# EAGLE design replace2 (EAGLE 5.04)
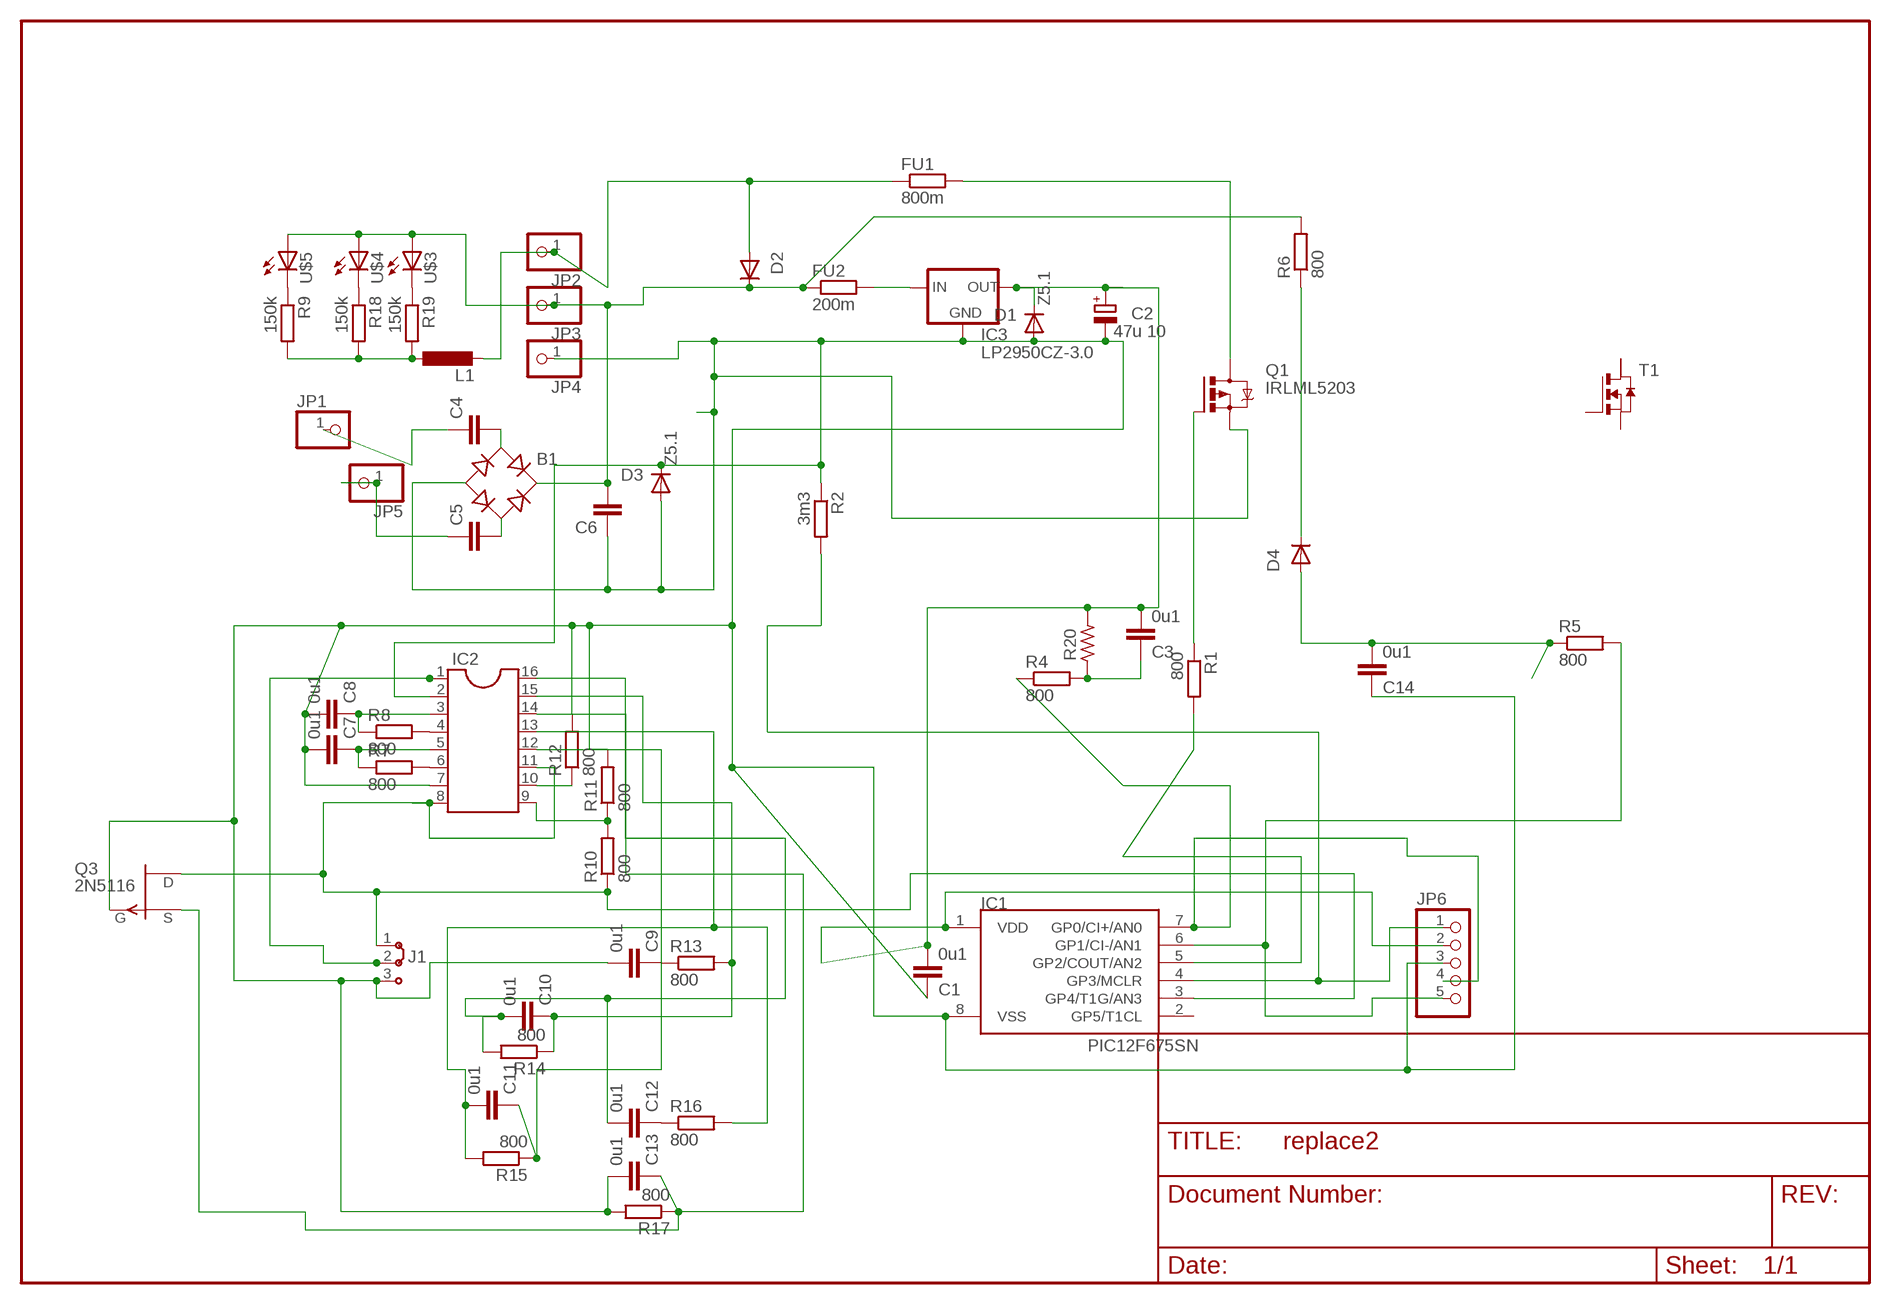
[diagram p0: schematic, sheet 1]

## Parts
B1  RB1A  [RB1A]
C1  0u1  C-EUC1206  [C1206]
C2  47u 10  CPOL-EUE2.5-5  [E2,5-5]
C3  0u1  C-EUC1206  [C1206]
C4  C-EU050-025X075  [C050-025X075]
C5  C-EU050-025X075  [C050-025X075]
C6  C-EU050-025X075  [C050-025X075]
C7  0u1  C-EUC1206  [C1206]
C8  0u1  C-EUC1206  [C1206]
C9  0u1  C-EUC1206  [C1206]
C10  0u1  C-EUC1206  [C1206]
C11  0u1  C-EUC1206  [C1206]
C12  0u1  C-EUC1206  [C1206]
C13  0u1  C-EUC1206  [C1206]
C14  0u1  C-EUC1206  [C1206]
D1  Z5.1  DIODE-MINIMELF  [MINIMELF]
D2  DIODE-MELF-MLL41  [MELF-MLL41]
D3  Z5.1  DIODE-MINIMELF  [MINIMELF]
D4  DIODE-MICROMELF-R  [MICROMELF-R]
FU1  800m  R-EU_0204/5  [0204/5]
FU2  200m  R-EU_0204/5  [0204/5]
IC1  PIC12F675SN  [SO-08]
IC2  DIL16  [DIL16]
IC3  LP2950CZ-3.0  [TO92]
J1  J2X2MM  [04C]
JP1  PINHD-1X1  [1X01]
JP2  PINHD-1X1  [1X01]
JP3  PINHD-1X1  [1X01]
JP4  PINHD-1X1  [1X01]
JP5  PINHD-1X1  [1X01]
JP6  PINHD-1X5  [1X05]
L1  L-EU0207/7  [0207/7]
Q1  IRLML5203  [MICRO3]
Q3  2N5116  [TO18]
R1  800  R-EU_R1206  [R1206]
R2  3m3  R-EU_R1206  [R1206]
R4  800  R-EU_R1206  [R1206]
R5  800  R-EU_R1206  [R1206]
R6  800  R-EU_R1206  [R1206]
R7  800  R-EU_R1206  [R1206]
R8  800  R-EU_R1206  [R1206]
R9  150k  R-EU_R1206  [R1206]
R10  800  R-EU_R1206  [R1206]
R11  800  R-EU_R1206  [R1206]
R12  800  R-EU_R1206  [R1206]
R13  800  R-EU_R1206  [R1206]
R14  800  R-EU_R1206  [R1206]
R15  800  R-EU_R1206  [R1206]
R16  800  R-EU_R1206  [R1206]
R17  800  R-EU_R1206  [R1206]
R18  150k  R-EU_R1206  [R1206]
R19  150k  R-EU_R1206  [R1206]
R20  R_X0207/5V  [0207/5V]
T1  NMOSSOT223  [SOT223]
U$3  LED5MM  [LED5MM]
U$4  LED5MM  [LED5MM]
U$5  LED5MM  [LED5MM]

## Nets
GND: B1.- C1.1 C2.- C6.1 C7.2 C8.2 C9.2 C13.2 C14.1 D1.A D3.A D3.C IC1.8(VSS) IC2.2 IC2.7 IC3.2(GND) J1.3 JP4.1 JP6.3 Q1.2(S) Q3.2(G) R2.1 R11.2 R12.2 R17.2
N$1: B1.+ C6.2 D2.C FU2.1 JP3.1 R6.2 U$3.A U$4.A U$5.A
N$4: D2.A FU1.1 JP2.1 L1.2
N$7: Q1.1(G) R1.1
N$8: FU2.2 IC3.3(IN)
N$9: FU1.2 Q1.3(D)
N$10: D4.C R6.1
N$12: IC1.4(GP3/MCLR) JP6.1 R2.2
N$13: C14.2 D4.A R5.1
N$14: IC1.5(GP2/COUT/AN2) R1.2
N$23: C3.1 R4.2 R20.1
N$29: IC1.7(GP0/CI+/AN0) JP6.4 R4.1
N$30: IC1.6(GP1/CI-/AN1) JP6.5 R5.2
N$32: B1.AC2 C5.2
N$33: B1.AC1 C4.2
N$34: IC1.3(GP4/T1G/AN3) IC2.8 IC2.11 J1.1 Q3.3(D) R10.1
N$35: C4.1 JP1.1
N$37: C5.1 JP5.1
N$38: R9.1 U$5.K(C)
N$39: IC2.1 J1.2
N$40: C8.1 IC2.3 R8.1
N$41: IC2.6 R7.2
N$42: IC2.4 R8.2
N$43: C7.1 IC2.5 R7.1
N$44: IC2.10 R12.1
N$45: IC2.9 R10.2 R11.1
N$46: C9.1 R13.1
N$47: C10.1 IC2.15 R13.2 R14.1
N$48: C11.1 IC2.12 R15.1
N$49: C12.1 R16.1
N$50: C13.1 IC2.14 Q3.1(S) R17.1
N$51: C11.2 IC2.13 R15.2 R16.2
N$53: C10.2 C12.2 IC2.16 R14.2
N$54: R18.1 U$4.K(C)
N$55: R19.1 U$3.K(C)
N$58: L1.1 R9.2 R18.2 R19.2
V2CC: C1.2 C2.+ C3.2 D1.C IC1.1(VDD) IC3.1(OUT) JP6.2 R20.2
Unconnected: IC1.2(GP5/T1CL) T1.1(G) T1.2(D) T1.3(S) T1.4(D2)

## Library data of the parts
B1 = rectifier:RB1A: RECTIFIER 1 A
C1 C3-C14 = rcl:C-EU: CAPACITOR, European symbol
C2 = rcl:CPOL-EU: POLARIZED CAPACITOR, European symbol
D1-D4 = diode:DIODE-: DIODE
FU1 FU2 R1 R2 R4-R19 = rcl:R-EU_: RESISTOR, European symbol
IC1 = microchip-3:PIC12F6*: uPC nW 1k Program Flash memory 2x Timer Comparator 10b A/D converter/ 4xIN
IC2 = ic-package:DIL16: Dual In Line
IC3 = v-reg:LP2950?*: Source: http://cache.national.com/ds/LP/LP2950.pdf
J1 = jumper:J2: Jumper switch 2 x 2.5 mm
JP1-JP5 = pinhead:PINHD-1X1: PIN HEADER
JP6 = pinhead(2):PINHD-1X5: PIN HEADER
L1 = rcl:L-EU: INDUCTOR, European symbol
Q1 = transistor-power:IRLML5203: HEXFET P-Channel Power MOSFET
Q3 = transistor-fet:2N5116: P-Channel Junction FET Source: Vishay 70260.pdf
R20 = rc-master:R_: RESISTOR
T1 = zetex:NMOSSOT223: MOS FET
U$3-U$5 = led(3):LED: LED

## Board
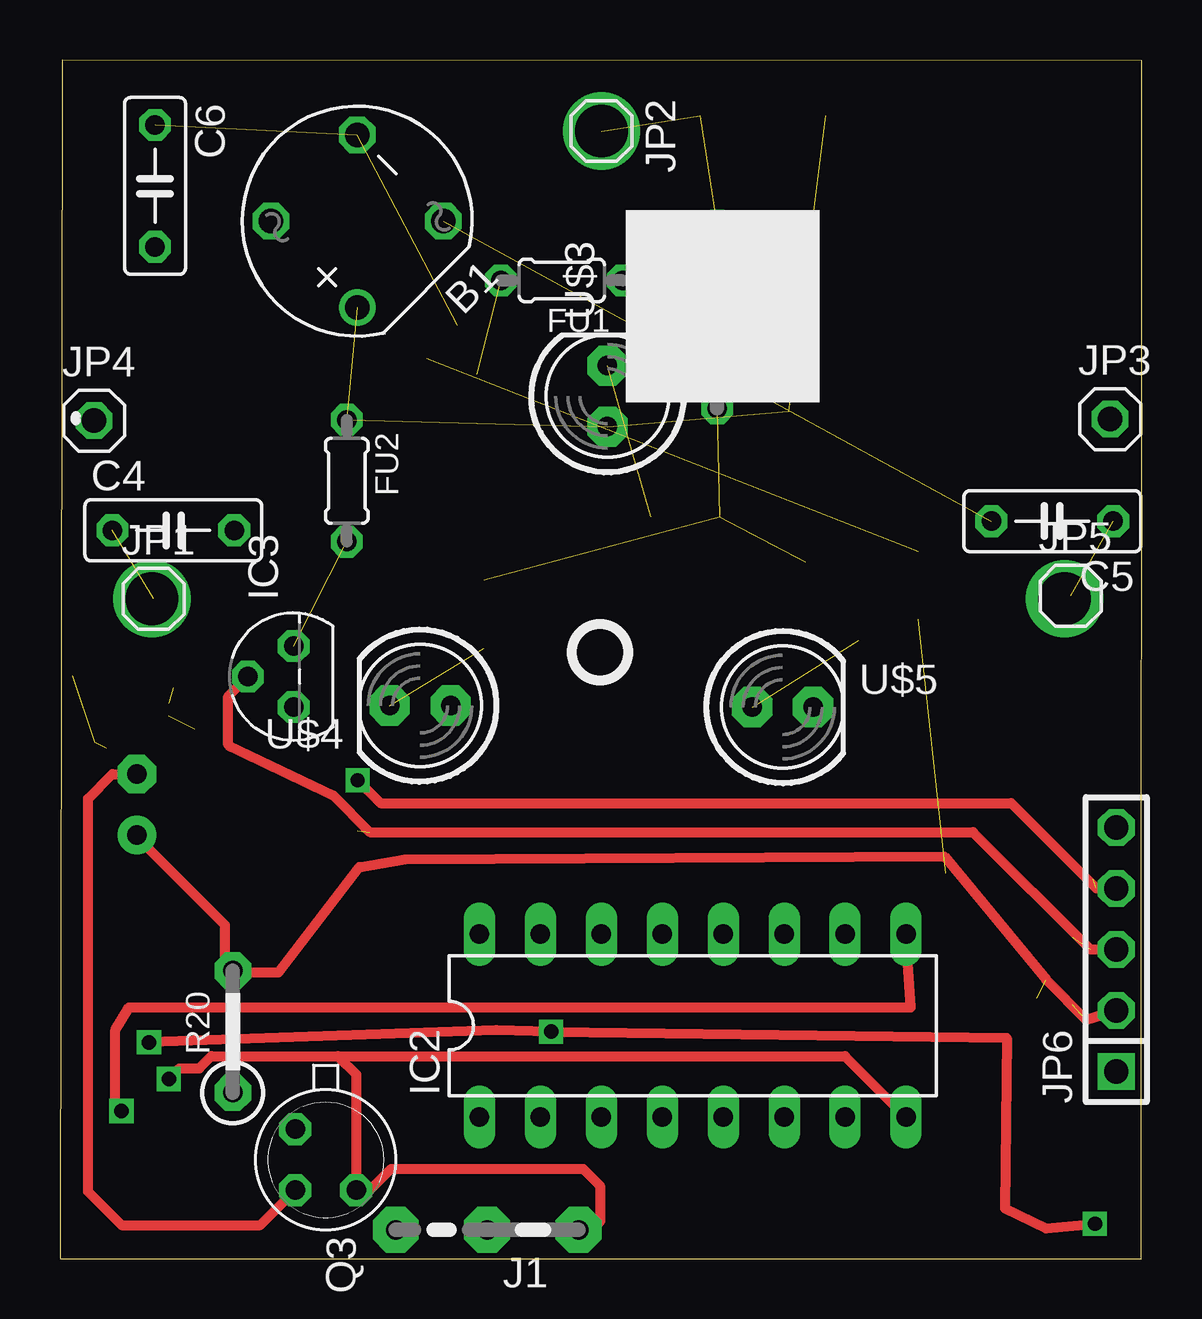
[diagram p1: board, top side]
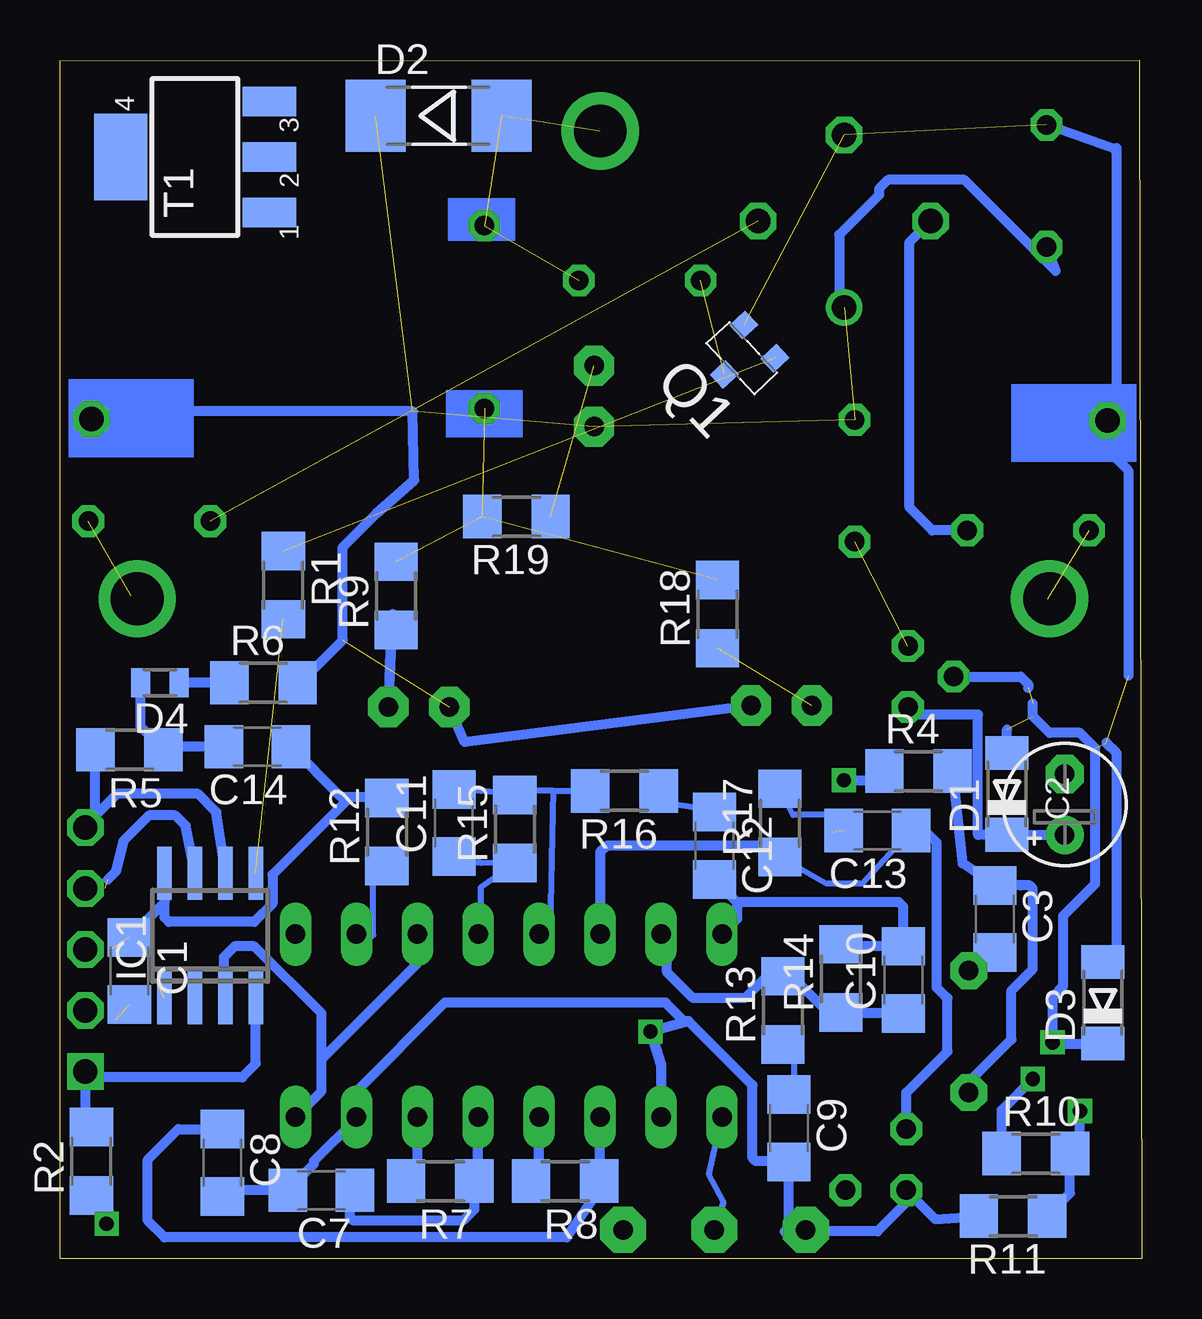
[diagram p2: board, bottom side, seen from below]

Size 45.09 x 49.94 mm. Coordinates in mm from the lower left corner, seen from the top.
Outline: 0,0 45.07,0 45.08,49.91 0.09,49.94 0,0
Copper layers (1*16): Top 0.035mm / dielectric 1.5mm / Bottom 0.035mm
Design rules "default": minimum track width 10mil, minimum drill 24mil, track to track 8mil, track to pad 8mil, pad to pad 8mil, via to via 8mil, smd to smd 8mil, copper to edge 40mil, drill to drill 8mil, minimum pad ring 10mil, minimum via ring 8mil, stop-mask expansion 4mil, vias tented up to drill 0mil, thermal gap 10mil

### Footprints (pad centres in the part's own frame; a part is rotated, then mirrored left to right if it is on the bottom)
RB1A = drill 1.016 round: + -2.54,2.54 | drill 1.016 octagon: - 2.54,-2.54; AC1 2.54,2.54; AC2 -2.54,-2.54
C1206 = smd 1.6 x 1.8: 1 -1.4,0; 2 1.4,0
E2,5-5 = drill 0.813 pad 1.6 round: + -1.27,0 | drill 0.813 pad 1.6 octagon: - 1.27,0
C050-025X075 = drill 0.813 octagon: 1 -2.54,0; 2 2.54,0
MINIMELF = smd 1.4 x 1.8: A 1.7,0; C -1.7,0
MELF-MLL41 = smd 2.5 x 3: A 2.625,0; C -2.625,0
MICROMELF-R = smd 0.8 x 1.2: A 0.8,0; C -0.8,0
0204/5 = drill 0.813 octagon: 1 -2.54,0; 2 2.54,0
SO-08 = smd 0.6 x 2.2: 1 -1.905,-2.6; 2 -0.635,-2.6; 3 0.635,-2.6; 4 1.905,-2.6; 5 1.905,2.6; 6 0.635,2.6; 7 -0.635,2.6; 8 -1.905,2.6
DIL16 = drill 0.813 long: 1 -8.89,-3.81; 2 -6.35,-3.81; 3 -3.81,-3.81; 4 -1.27,-3.81; 5 1.27,-3.81; 6 3.81,-3.81; 7 6.35,-3.81; 8 8.89,-3.81; 9 8.89,3.81; 10 6.35,3.81; 11 3.81,3.81; 12 1.27,3.81; 13 -1.27,3.81; 14 -3.81,3.81; 15 -6.35,3.81; 16 -8.89,3.81
TO92 = drill 0.813 octagon: 1 -1.27,0; 2 0,1.905; 3 1.27,0
04C = drill 0.813 pad 1.905 octagon: 1 -1.905,0; 2 1.905,0; 3 5.715,0
1X01 = drill 1.016 octagon: 1 0,0
1X05 = drill 1.016 square: 1 -5.08,0 | drill 1.016 octagon: 2 -2.54,0; 3 0,0; 4 2.54,0; 5 5.08,0
0207/7 = drill 0.813 octagon: 1 -3.81,0; 2 3.81,0
MICRO3 = smd 0.8 x 0.9: 1 -0.95,-1; 2 0.95,-1; 3 0,1
TO18 = drill 0.813 octagon: 1 -1.27,-1.27; 2 1.27,-1.27; 3 1.27,1.27
R1206 = smd 1.6 x 1.803: 1 -1.422,0; 2 1.422,0
0207/5V = drill 0.813 pad 1.524 octagon: 1 -2.54,0; 2 2.54,0
SOT223 = smd 1.219 x 2.235: 1 -2.311,-3.099; 2 0,-3.099; 3 2.311,-3.099 | smd 3.6 x 2.2: 4 0,3.099
LED5MM = drill 0.813 pad 1.676 octagon: A -1.27,0; K 1.27,0

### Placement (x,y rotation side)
B1  12.39,43.23 135 top
C1  42.19,11.99 270 bottom
C2  3.2,18.92 90 bottom
C3  6.12,14.16 270 bottom
C4  4.72,30.35 0 top
C5  41.36,30.73 180 top
C6  3.96,44.7 270 top
C7  34.19,2.85 180 bottom
C8  38.32,4 270 bottom
C9  14.7,5.43 270 bottom
C10  9.93,11.62 90 bottom
C11  28.66,18.16 90 bottom
C12  17.81,17.2 270 bottom
C13  11.01,17.84 180 bottom
C14  36.86,21.33 180 bottom
D1  5.61,19.36 90 bottom
D2  29.3,47.62 0 bottom
D3  1.61,10.66 90 bottom
D4  40.92,24 180 bottom
FU1  20.92,40.76 180 top
FU2  11.95,32.41 270 top
IC1  38.82,13.46 0 bottom
IC2  26.38,9.71 0 top
IC3  9.74,24.25 90 top
J1  19.71,1.2 180 top
JP1  3.9,27.49 0 top
JP2  22.57,46.98 270 top
JP3  43.78,34.98 0 top
JP4  1.42,34.92 0 top
JP5  42.13,27.62 0 top
JP6  44.03,12.89 90 top
L1  27.39,39.24 90 top
Q1  16.66,37.52 133.1 bottom
Q3  11.07,4.12 270 top
R1  35.78,28.06 270 bottom
R2  43.78,4.06 90 bottom
R4  9.3,20.32 0 bottom
R5  42.19,21.2 180 bottom
R6  36.6,24 0 bottom
R7  29.24,3.23 180 bottom
R8  24.03,3.23 180 bottom
R9  31.08,27.62 90 bottom
R10  4.41,4.38 0 bottom
R11  5.36,1.77 180 bottom
R12  31.46,17.78 90 bottom
R13  14.95,10.35 90 bottom
R14  12.53,11.68 90 bottom
R15  26.12,17.9 90 bottom
R16  21.55,19.49 180 bottom
R17  15.07,18.16 90 bottom
R18  17.68,26.86 90 bottom
R19  26.06,30.92 180 bottom
R20  7.2,9.46 90 top
T1  39.46,45.91 90 bottom
U$3  22.82,35.94 90 top
U$4  15.01,23.05 180 top
U$5  30.12,22.98 0 top

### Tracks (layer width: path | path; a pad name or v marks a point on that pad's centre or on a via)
GND  (via drill 0.6)  (8 unrouted)
  Top 0.406: C2.- 2.18,20.19 1.17,19.17 1.17,2.79 2.57,1.39 8.34,1.39 Q3.2 | JP6.3 42.95,12.88 38.06,17.78 12.92,17.78 11.39,19.3 7.01,21.4 7.01,23.43 IC3.2 | v43.14,1.46 41.11,1.27 39.4,2.09 39.46,9.2 v20.47,9.46 18.19,9.52 v3.71,9.01
  Bottom 0.254: C13.2 13.03,18.5 14.53,18.5 R17.2
  Bottom 0.406: R11.2 8.6,1.65 Q3.2 9.8,2.34 11.01,1.14 14.88,1.14 J1.3 14.7,1.7 C9.2 14.73,4.06 16.09,4.06 16.22,4.19 16.22,7.23 18.89,9.9 | C8.2 38.06,2.85 C7.2 34.51,3.94 34.51,4.06 32.73,5.84 IC2.7 32.73,6.98 29.05,10.66 19.84,10.66 19.08,9.9 18.89,9.9 | C1.1 40.73,14.85 IC1.8 40.73,14.22 40.54,14.03 36.98,14.03 36.22,14.79 36.22,16 32.98,19.24 | 32.98,19.24 31.5,19.24 R12.2 | IC2.2 20.03,8.06 v20.47,9.46 18.89,9.9 | v43.14,1.46 43.27,1.75 R2.1 | D3.C 3.66,8.96 v3.71,9.01 3.71,10.92 3.26,11.36 3.26,14.28 1.93,15.62 1.93,21.27 2.57,21.9 3.84,21.9 4.53,22.6 4.53,23.13 | D1.A 5.61,22.05 | IC3.2 5.04,24.25 4.72,23.93 4.72,23.78 | 32.98,19.24 33.36,19.24 C14.1 | 1.46,21.5 1.04,21.08 1.04,12.93 D3.A | 0.53,24.29 0.53,32.82 1.42,33.71 JP4.1 1.04,35.3 1.04,46.29 1.1,46.22 C6.1
N$1  (5 unrouted)
  Bottom 0.406: 43.71,34.92 JP3.1 43.46,35.3 30.38,35.3 30.32,32.44 31.9,31.05 33.3,29.65 33.3,25.78 35.08,24 R6.2 | U$4.A 28.22,21.52 U$5.A | C6.2 3.58,41.14 7.39,44.95 10.57,44.95 10.95,44.57 10.95,44.32 12.6,42.67 12.6,39.85 B1.+
N$2  (via drill 2.2)
  other vias: 3.84,27.49
N$3  (via drill 2.2)
  other vias: 41.87,27.49
N$4  (3 unrouted)
N$5  (via drill 2.2)
  other vias: 22.57,46.98
N$7  (1 unrouted)
N$8  (1 unrouted)
N$9  (1 unrouted)
N$10
  Bottom 0.406: R6.1 D4.C
N$12
  Bottom 0.406: IC1.4 36.92,8.12 37.49,7.55 43.78,7.55 JP6.1 44.03,5.74 R2.2
N$13
  Bottom 0.406: C14.2 40.64,21.33 R5.1 41.72,22.16 D4.A
N$14  (1 unrouted)
N$23
  Bottom 0.406: R20.1 7.2,7.36 5.42,9.14 5.42,11.17 4.53,12.06 4.53,15.43 4.66,15.55 5.04,15.55 C3.1 7.45,16.47 R4.2
N$29  (via drill 0.6)  (1 unrouted)
  Top 0.406: JP6.4 43.21,15.43 39.65,18.98 13.36,18.98 v12.41,19.93
  Bottom 0.406: IC1.7 39.84,18.03 40.28,18.47 41.36,18.47 42.44,17.39 42.76,16.12 43.08,15.81 | v12.41,19.93 11.1,19.93 R4.1
N$30
  Bottom 0.406: IC1.6 38.57,18.6 39.33,19.36 42.7,19.36 43.78,18.28 43.78,17.78 JP6.5 43.61,18.39 R5.2
N$32  (1 unrouted)
N$33
  Bottom 0.406: C4.2 8.73,30.35 9.68,31.3 9.68,42.35 B1.AC1
N$34  (via drill 0.6)
  Top 0.406: v4.53,7.49 4.98,7.93 5.8,7.93 6.31,8.44 11.58,8.44 | 11.58,8.44 32.73,8.44 IC2.8 | 11.58,8.44 12.34,7.68 Q3.3 12.92,2.85 13.81,3.74 21.81,3.74 22.5,3.04 22.5,1.52 J1.1
  Bottom 0.406: R10.1 5.83,6.19 v4.53,7.49 | IC2.11 30.19,12.31 34.19,8.31 | 34.19,8.31 34.19,6.98 IC2.8 | 34.19,8.31 34.19,10.22 36.98,13.01 37.81,13.01 38.25,12.57 38.25,10.92 IC1.3
N$35  (1 unrouted)
N$37  (1 unrouted)
N$38
  Bottom 0.406: 31.2,26.86 U$5.K 31.27,26.48 R9.1
N$39
  Bottom 0.254: IC2.1 18.03,3.5 17.43,2.38 J1.2
N$40
  Bottom 0.406: C8.1 40.16,5.39 41.43,4.12 41.43,1.58 40.73,0.88 23.96,0.88 22.61,2.88 R8.1 22.57,3.27 IC2.3
N$41
  Bottom 0.406: IC2.6 30.19,3.7 R7.2
N$42
  Bottom 0.406: IC2.4 25.11,3.58 R8.2
N$43
  Bottom 0.406: C7.1 32.98,2.66 32.98,1.71 32.86,1.58 28.28,1.58 27.81,2.05 R7.1 27.65,3.4 IC2.5
N$44
  Bottom 0.254: R12.1 32.03,15.99 32.03,13.49 32.53,12.99 IC2.10
N$45  (via drill 0.6)
  Top 0.406: IC2.9 35.46,10.47 2.88,10.47 2.31,9.52 2.31,6.41 v2.57,6.16
  Bottom 0.406: v2.57,6.16 2.57,4.8 R10.2 2.98,2.73 R11.1
N$46
  Bottom 0.254: C9.1 14.47,6.92 14.47,8.92 14.23,8.97 R13.1
N$47
  Bottom 0.406: C10.1 12.49,10.21 R14.1 13.08,10.26 14.25,11.42 14.61,11.42 R13.2 15.62,11.77 16.54,10.85 18.69,10.85 19.77,11.93 19.77,13.27 IC2.15
N$48
  Bottom 0.254: C11.1 28.03,16.5 27.53,16.5 R15.1 27.53,15.49 27.53,12.99 IC2.12
N$49
  Bottom 0.254: C12.1 18.85,18.84 20.03,19 R16.1
N$50
  Bottom 0.254: C13.1 11.63,15.62 13.13,15.62 R17.1
  Bottom 0.406: IC2.14 22.57,16.95 22.31,17.2 15.54,17.2 R17.1 | Q3.1 9.8,6.92 8.09,8.63 8.09,10.85 8.53,11.3 8.53,17.33 9.04,17.84 C13.1
N$51
  Bottom 0.254: C11.2 28.03,19.5 27.53,19.5 R15.2 26.03,19.5 24.52,19.5 | 24.52,19.5 23.03,19.5 R16.2 | 24.52,19.5 24.64,13.76 IC2.13
N$53
  Bottom 0.406: 16.86,14.85 10.12,14.85 9.93,14.66 C10.2 12.45,13.02 R14.2 | 16.86,14.85 C12.2 | 16.86,14.85 16.86,14.15 IC2.16
N$54  (1 unrouted)
N$55  (1 unrouted)
N$58  (3 unrouted)
V2CC  (2 unrouted)
  Top 0.406: JP6.2 42.76,9.96 41.11,11.61 36.86,16.76 14.38,16.63 12.47,16.32 9.11,11.93 7.26,11.93 R20.2 6.88,12.31 6.88,13.9 3.2,17.59 C2.+
  Bottom 0.406: C3.2 6.19,13.01 R20.2 | C2.+ 5.61,17.65 D1.C 6.82,17.66 6.82,22.66 9.74,22.66 IC3.1
(copper drawn outside any net)
  shapes: Bottom area x4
